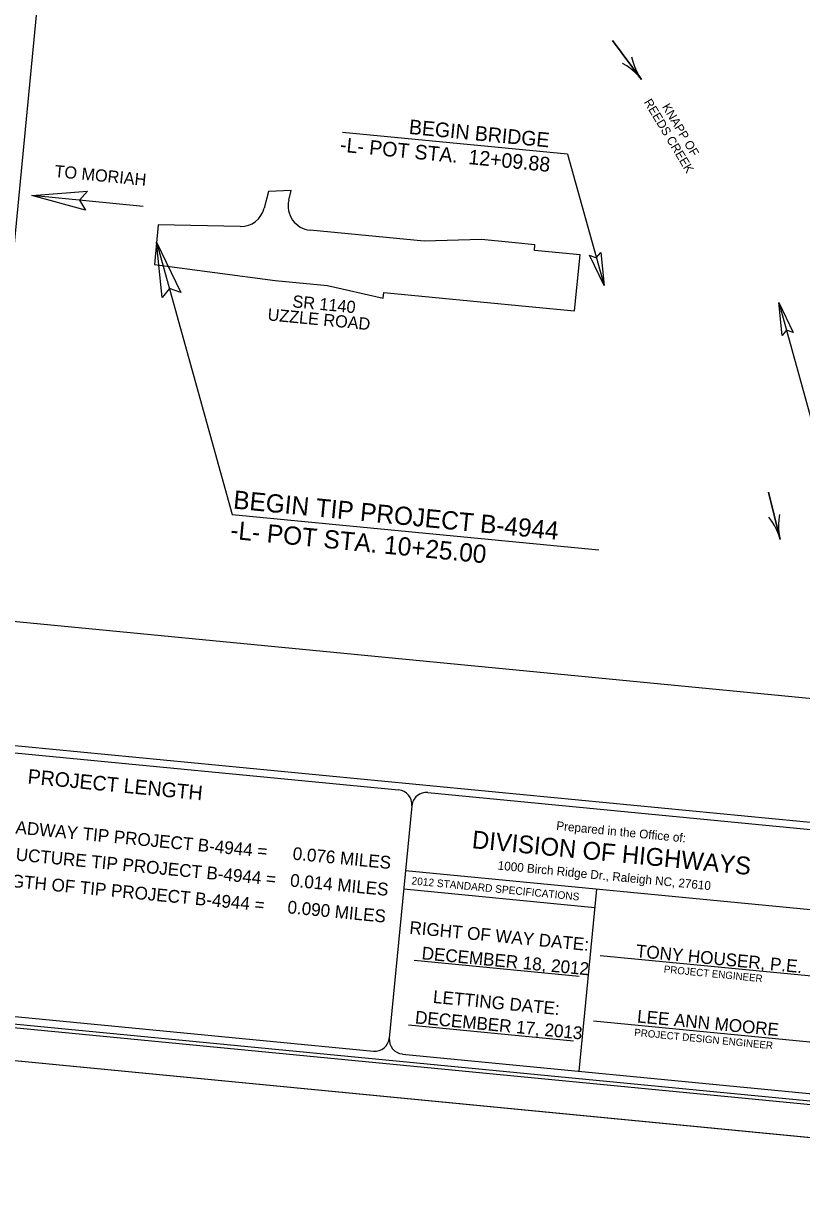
# Model space of a CAD drawing. Extents: x 2060574 to 2063008, y 912203 to 913082.
# Drawn here: x 2061000.5 to 2061320.5, y 912328.1 to 912811 of the extents above; entities that cross this region are included whole.
import ezdxf

# ---------------------------------------------------------------- set-up
doc = ezdxf.new("R2010")
doc.units = 0
for name, color, linetype in [('Default', 7, 'Continuous'), ('Exist PHM Water Shape', 7, 'Continuous'), ('Prop Shade Medium', 7, 'Continuous'), ('Prop Terminator CELL', 7, 'Continuous'), ('Sheet Cutting Line CELL', 7, 'Continuous'), ('Sheet Data Field CELL', 7, 'Continuous'), ('Sheet Plot Border Inside CELL', 7, 'Continuous'), ('Sheet Plot Border Outside CELL', 7, 'Continuous'), ('Sheet Title CELL', 7, 'Continuous')]:
    doc.layers.add(name, color=color, linetype=linetype)

# ---------------------------------------------------------------- blocks, each defined once
blk = doc.blocks.new('EXIST HYDRO RIVER FLOW ARROW')
at = {"layer": 'Default'}
blk.add_line((0, 0), (0, 0), dxfattribs=at)
blk.add_lwpolyline([(0, 0.04575), (0.03775, 0.03), (0.07725, 0.01725), (0.118, 0.00775), (0.159, 0.0015), (0.2, 0), (-0.2, 0), (0.2, 0), (0.159, -0.0015), (0.118, -0.00775), (0.07725, -0.01725), (0.03775, -0.03), (0, -0.04575)], dxfattribs=at)

msp = doc.modelspace()

# ---------------------------------------------------------------- linework, layer by layer
at = {"layer": 'Prop Shade Medium'}
for p, q in [((2061101.19, 912741.81), (2061099.51, 912735.06)), ((2061110.59, 912742.29), (2061101.19, 912741.81)), ((2061109.6, 912738.34), (2061110.59, 912742.29)), ((2061055.91, 912728.18), (2061054.33, 912711.84)), ((2061089.6, 912727.49), (2061055.91, 912728.18)), ((2061165.24, 912721.43), (2061118.34, 912725.96)), ((2061227.17, 912692.75), (2061229.4, 912715.81)), ((2061054.33, 912711.84), (2061103.93, 912705.25)), ((2061103.93, 912705.25), (2061125.49, 912703.17))]:
    msp.add_line(p, q, dxfattribs=at)
for points in [[(2061229.4, 912715.81), (2061210.61, 912717.63), (2061210.84, 912719.95), (2061201.36, 912720.87), (2061188.85, 912722.09), (2061165.24, 912721.43)], [(2061125.49, 912703.17), (2061148.44, 912698.02), (2061148.66, 912700.34), (2061148.66, 912700.34), (2061208.38, 912694.57), (2061227.17, 912692.75)]]:
    msp.add_lwpolyline(points, dxfattribs=at)
for centre, start, end in [((2061119.3, 912735.91), 165.9729, 264.4787), ((2061089.81, 912737.48), 268.8252, 345.9729)]:
    msp.add_arc(centre, 10, start, end, dxfattribs=at)
at = {"layer": 'Prop Terminator CELL'}
for points in [[(2061025.92, 912734.16), (2061003.9, 912740.18), (2061026.81, 912741.99), (2061023.56, 912738.28)], [(2061057.5, 912698.29), (2061055.22, 912721.01), (2061065.12, 912700.28), (2061060.49, 912701.98)], [(2061237.87, 912716.85), (2061239.24, 912703.22), (2061233.3, 912715.66), (2061236.07, 912714.64)], [(2061312.52, 912682.64), (2061311.15, 912696.27), (2061317.09, 912683.83), (2061314.32, 912684.85)]]:
    msp.add_lwpolyline(points, close=True, dxfattribs=at)
at = {"layer": 'Sheet Cutting Line CELL'}
msp.add_line((2060574.1, 912425.31), (2061579.81, 912328.1), dxfattribs=at)
at = {"layer": 'Sheet Data Field CELL'}
for p, q in [((2061224.25, 912757.24), (2061131.62, 912766.2)), ((2061224.25, 912757.24), (2061239.24, 912703.22)), ((2061049.66, 912735.76), (2061003.9, 912740.18)), ((2061055.22, 912721.01), (2061086.28, 912609.03)), ((2061311.15, 912696.27), (2061326.15, 912642.22)), ((2061086.28, 912609.03), (2061237.16, 912594.44))]:
    msp.add_line(p, q, dxfattribs=at)
msp.add_lwpolyline([(2061010.39, 912861.5), (2061587.46, 912805.72), (2061558.93, 912510.54), (2060981.86, 912566.32)], close=True, dxfattribs=at)
at = {"layer": 'Sheet Plot Border Inside CELL'}
msp.add_lwpolyline([(2060583.16, 912437.96), (2061578.42, 912341.76), (2061639.33, 912971.88), (2060644.07, 913068.09)], close=True, dxfattribs=at)
at = {"layer": 'Sheet Plot Border Outside CELL'}
msp.add_lwpolyline([(2061643.31, 912985.03), (2060637.6, 913082.24), (2060574.1, 912425.31), (2061579.81, 912328.1)], close=True, dxfattribs=at)
at = {"layer": 'Sheet Title CELL'}
for p, q in [((2060725.07, 912540.32), (2061573.11, 912458.35)), ((2060927.83, 912517.7), (2061154.77, 912495.76)), ((2061166.72, 912494.62), (2061336.92, 912478.16)), ((2061160.17, 912489.22), (2061150.93, 912393.67)), ((2061339.73, 912444.88), (2061157.58, 912462.5)), ((2061235.41, 912447.28), (2061156.85, 912454.88)), ((2061236.15, 912454.9), (2061228.92, 912380.1)), ((2061212.78, 912449.47), (2061212.78, 912449.47)), ((2061237.67, 912427.63), (2061330.33, 912418.66)), ((2061229.07, 912419.06), (2061161.13, 912425.62)), ((2061195.08, 912422.33), (2061195.08, 912422.33)), ((2061226.73, 912392.4), (2061158.8, 912398.96)), ((2061234.86, 912400.77), (2061328.18, 912391.75))]:
    msp.add_line(p, q, dxfattribs=at)
for points in [[(2060681.25, 912430.02), (2061565.13, 912344.58)], [(2060917.44, 912410.2), (2061144.38, 912388.26)], [(2061156.33, 912387.12), (2061326.53, 912370.66)]]:
    msp.add_lwpolyline(points, dxfattribs=at)
for centre, start, end in [((2061154.2, 912489.82), 354.4787, 84.4787), ((2061166.15, 912488.67), 84.4787, 174.4787), ((2061144.96, 912394.27), 264.4787, 354.4787), ((2061156.91, 912393.12), 174.4787, 264.4787)]:
    msp.add_arc(centre, 6, start, end, dxfattribs=at)

# ---------------------------------------------------------------- block references
at = {"layer": 'Exist PHM Water Shape', "xscale": 50.00000000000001}
for p, yscale, rotation in [((2061248.72, 912795.94), 50.00000000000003, -53.392905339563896), ((2061309.26, 912608.44), 50.000000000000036, -75.96373668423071)]:
    msp.add_blockref('EXIST HYDRO RIVER FLOW ARROW', p, dxfattribs=dict(at, yscale=yscale, rotation=rotation))

# ---------------------------------------------------------------- texts
at = {"layer": 'Exist PHM Water Shape'}
for s, p in [('REEDS CREEK', (2061255.53, 912778.66)), ('KNAPP OF', (2061262.97, 912776.74))]:
    msp.add_text(s, height=3.6, rotation=300.9372, dxfattribs=at).set_placement(p)
at = {"layer": 'Sheet Data Field CELL'}
for s, height, p in [('BEGIN BRIDGE', 6, (2061158.82, 912765.58)), ('-L- POT STA.  12+09.88', 6, (2061130.47, 912758.27)), ('TO MORIAH', 5, (2061013.04, 912747.83)), ('SR 1140', 5, (2061110.91, 912694.28)), ('UZZLE ROAD', 5, (2061100.7, 912688.9)), ('BEGIN TIP PROJECT B-4944', 7.5, (2061086.52, 912611.51)), ('-L- POT STA. 10+25.00', 7.5, (2061085.32, 912599.07)), ('LENGTH OF ROADWAY TIP PROJECT B-4944 =', 5.2501, (2060944.61, 912482.9)), ('LENGTH OF STRUCTURE TIP PROJECT B-4944 =', 5.2501, (2060941.19, 912472.14)), ('0.076 MILES', 5.2501, (2061111, 912467.08)), ('TOTAL LENGTH OF TIP PROJECT B-4944 =', 5.2501, (2060957.04, 912459.52)), ('0.014 MILES', 5.2501, (2061109.93, 912456.05)), ('0.090 MILES', 5.2501, (2061108.86, 912445.03)), ('TONY HOUSER, P.E.', 5.2501, (2061252.19, 912427)), ('DECEMBER 18, 2012', 5.2501, (2061164.07, 912426.11)), ('DECEMBER 17, 2013', 5.2501, (2061161.35, 912399.73)), ('LEE ANN MOORE', 5.2501, (2061252.68, 912400.11))]:
    msp.add_text(s, height=height, rotation=354.4787, dxfattribs=at).set_placement(p)
at = {"layer": 'Sheet Title CELL'}
for s, height, p in [('PROJECT LENGTH', 5.9998, (2061001.98, 912498.39)), ('Prepared in the Office of:', 3.5996, (2061219.49, 912479.29)), ('DIVISION OF HIGHWAYS', 7.3123, (2061184.7, 912471.81)), ('1000 Birch Ridge Dr., Raleigh NC, 27610', 3.6, (2061195.4, 912462.97)), ('2012 STANDARD SPECIFICATIONS', 3.12, (2061159.96, 912456.9)), ('RIGHT OF WAY DATE: ', 5.2499, (2061159.03, 912436.62)), ('PROJECT ENGINEER', 2.9997, (2061263.72, 912420.59)), ('LETTING DATE:', 5.2499, (2061168.73, 912408.16)), ('PROJECT DESIGN ENGINEER', 2.9997, (2061251.57, 912394.6))]:
    msp.add_text(s, height=height, rotation=354.4787, dxfattribs=at).set_placement(p)

doc.saveas('drawing.dxf')
